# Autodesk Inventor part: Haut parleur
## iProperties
Created: 2010-07
Part Number: Haut parleur
Document SubType Name: Modeling
Designer: eric
Density: 1 g/cm^3
Mass: 1.4058 g
Surface Area: 11.7247 cm^2
Volume: 1.4058 cm^3
Author: eric
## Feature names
1. Extrusion3
2. Extrusion2
3. Extrusion1
